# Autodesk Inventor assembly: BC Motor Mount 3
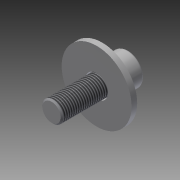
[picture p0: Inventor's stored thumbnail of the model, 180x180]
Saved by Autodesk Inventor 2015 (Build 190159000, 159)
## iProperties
Created: 2007-02
Part Number: BC Motor Mount 3
Document SubType Name: Assembly
Designer: Autodesk, Inc.
Mass: 40.8056 g
Surface Area: 39.4938 cm^2
Volume: 5.19155 cm^3
Density: 7.86 g/cm^3
ClientObjectVersion: 1
Author: Autodesk, Inc.
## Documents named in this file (4)
- C:\Users\Public\Documents\Autodesk\Inventor 2015\Samples\Models\Assemblies\Blower\Blower\Design Accelerator\BC Motor Mount 21.iam
- C:\Users\Public\Documents\Autodesk\Inventor 2015\Samples\Standard Parts\en-US\ANSI B18.22.1\ANSI B18.22.1 - 3_8 - wide - Type B.ipt
- C:\Users\Public\Documents\Autodesk\Inventor 2015\Samples\Standard Parts\en-US\ANSI B18.21.1\ANSI B18.21.1 - 0.375.ipt
- C:\Users\Public\Documents\Autodesk\Inventor 2015\Samples\Standard Parts\en-US\ANSI B18.3(13)\ANSI B18.3 - 3_8-24 UNF - 1(22).ipt
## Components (3 placed, 3 different names)
1. ANSI B18.22.1 - 3/8 - wide - Type B:1
2. ANSI B18.21.1 - 0.375:2
3. ANSI B18.3 - 3/8-24 UNF - 1:3
